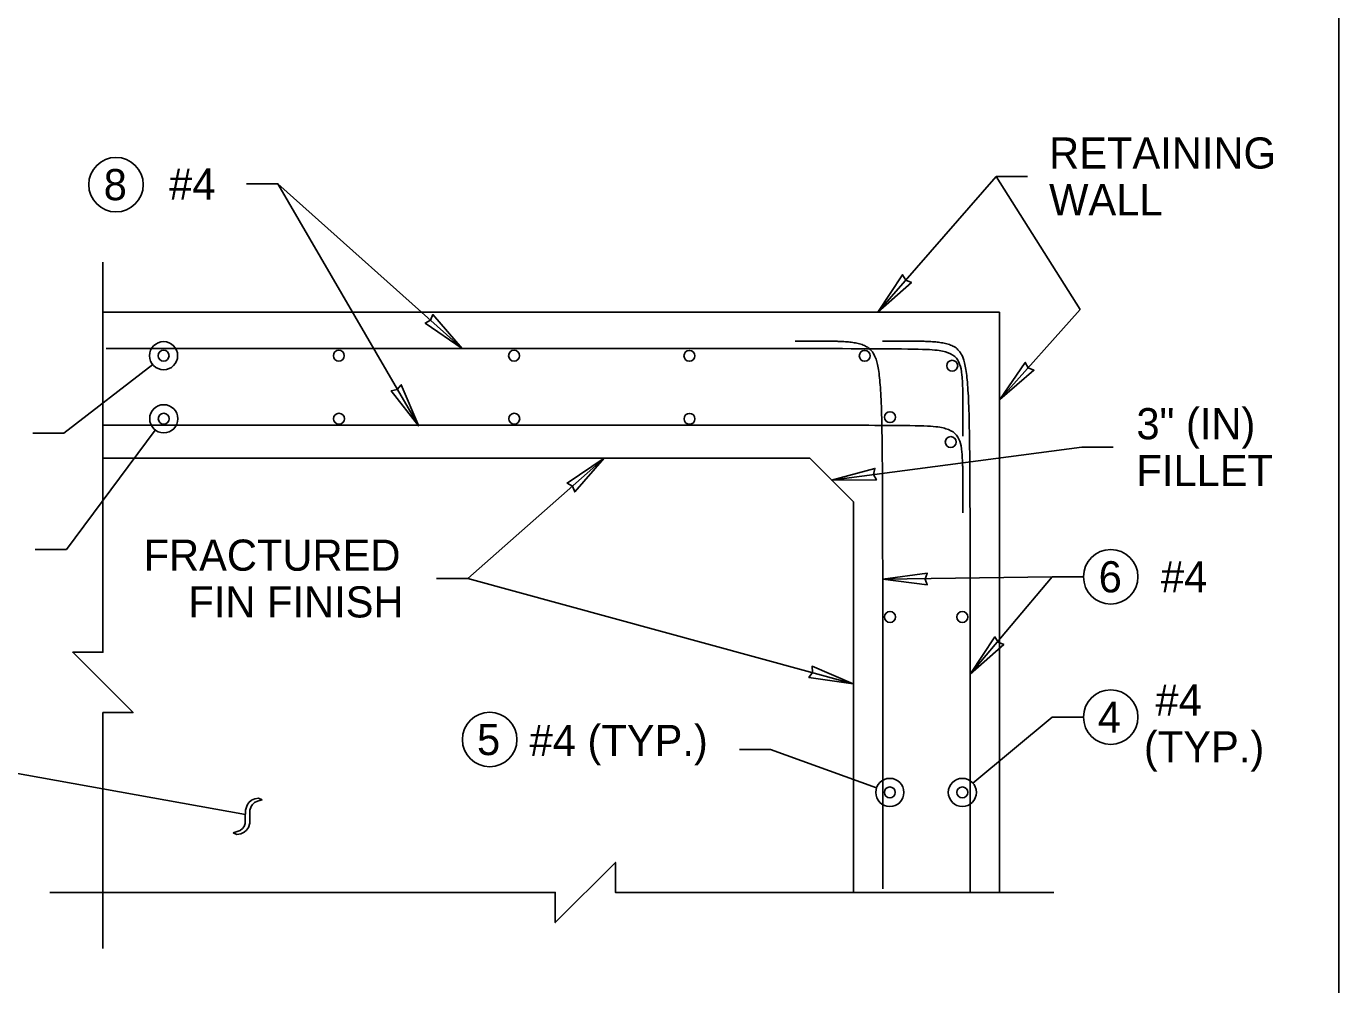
# Model space of a CAD drawing. Extents: x 99862 to 103680, y 99470 to 105076.
# Drawn here: x 102477 to 103151, y 103992 to 104485 of the extents above; entities that cross this region are included whole.
import ezdxf

# ---------------------------------------------------------------- set-up
doc = ezdxf.new("R2010")
doc.units = 0
for name, color, linetype in [('Level 1', 7, 'Continuous'), ('Level 14', 7, 'Continuous'), ('Level 15', 7, 'Continuous'), ('Level 2', 7, 'Continuous'), ('Level 20', 7, 'Continuous'), ('Level 34', 7, 'Continuous'), ('Level 35', 7, 'Continuous'), ('Level 36', 7, 'Continuous'), ('Level 38', 7, 'Continuous')]:
    doc.layers.add(name, color=color, linetype=linetype)

msp = doc.modelspace()

# ---------------------------------------------------------------- linework, layer by layer
at = {"layer": 'Level 1'}
msp.add_lwpolyline([(99862, 102999.5), (103151, 102999.5), (103151, 105075.5), (99862, 105075.5)], close=True, dxfattribs=at)
at = {"layer": 'Level 14'}
for points in [[(102516.3, 104010.95), (102516.3, 104132.04), (102531.79, 104132.04), (102500.82, 104163.02), (102516.3, 104163.02), (102516.3, 104363.37)], [(103004.71, 104039.64), (102779.54, 104039.64), (102779.54, 104055.12), (102748.57, 104024.15), (102748.57, 104039.64), (102489.1, 104039.64)]]:
    msp.add_lwpolyline(points, dxfattribs=at)
at = {"layer": 'Level 15'}
for p, q in [((102590.09, 104403.51), (102606.09, 104403.51)), ((102700.77, 104318.98), (102606.09, 104403.51)), ((102606.09, 104403.51), (102678.47, 104279.16)), ((102914.26, 104337.73), (102975.1, 104407.43)), ((102991.1, 104407.43), (102975.1, 104407.43)), ((103018.21, 104338.98), (102975.1, 104407.43)), ((102976.99, 104292.84), (103018.21, 104338.98)), ((102541.93, 104310.87), (102496.26, 104275.58)), ((102480.26, 104275.58), (102496.26, 104275.58)), ((102543.18, 104277.15), (102497.51, 104215.77)), ((102773.74, 104262.73), (102703.68, 104200.89)), ((103019.08, 104268.4), (102890.54, 104251.48)), ((103035.08, 104268.4), (103019.08, 104268.4)), ((102481.51, 104215.77), (102497.51, 104215.77)), ((102916.79, 104200.64), (103003.88, 104201.78)), ((102961.7, 104151.72), (103003.88, 104201.78)), ((103019.88, 104201.78), (103003.88, 104201.78)), ((102687.68, 104200.89), (102703.68, 104200.89)), ((102901.69, 104146.82), (102703.68, 104200.89)), ((102963.09, 104095.82), (103003.88, 104129.71)), ((103019.88, 104129.71), (103003.88, 104129.71)), ((102843.17, 104113.04), (102859.17, 104113.04)), ((102913.59, 104093.36), (102859.17, 104113.04)), ((102589.46, 104079.62), (102468.66, 104101.43)), ((102592.59, 104086.99), (102591.28, 104085.9)), ((102594.23, 104087.72), (102592.59, 104086.99)), ((102594.15, 104085.78), (102595.74, 104086.49)), ((102596.18, 104088.09), (102594.23, 104087.72)), ((102595.74, 104086.49), (102598.07, 104087.15)), ((102598.07, 104087.15), (102596.18, 104088.09)), ((102589.52, 104081.83), (102589.41, 104077.42)), ((102590.3, 104084.44), (102589.52, 104081.83)), ((102591.28, 104085.9), (102590.3, 104084.44)), ((102591.75, 104079.41), (102591.82, 104081.96)), ((102591.82, 104081.96), (102592.35, 104083.81)), ((102592.35, 104083.81), (102593.11, 104084.91)), ((102593.11, 104084.91), (102594.15, 104085.78)), ((102588.9, 104073.56), (102588.04, 104072.43)), ((102589.34, 104075), (102588.9, 104073.56)), ((102589.41, 104077.42), (102589.34, 104075)), ((102590.04, 104071.59), (102590.97, 104072.98)), ((102590.97, 104072.98), (102591.72, 104075.32)), ((102591.72, 104075.32), (102591.75, 104079.41)), ((102586.7, 104071.48), (102583.2, 104070.28)), ((102583.2, 104070.28), (102585.09, 104069.34)), ((102585.09, 104069.34), (102587.18, 104069.82)), ((102588.04, 104072.43), (102586.7, 104071.48)), ((102587.18, 104069.82), (102588.8, 104070.56)), ((102588.8, 104070.56), (102590.04, 104071.59))]:
    msp.add_line(p, q, dxfattribs=at)
for points in [[(102914.26, 104337.73), (102931.52, 104352.97), (102928.58, 104354.14), (102927.02, 104356.9)], [(102700.77, 104318.98), (102681.8, 104332.04), (102684.59, 104333.55), (102685.8, 104336.48)], [(102976.99, 104292.84), (102994.42, 104307.88), (102991.5, 104309.08), (102989.97, 104311.86)], [(102678.52, 104279.19), (102664.36, 104297.35), (102667.47, 104297.95), (102669.51, 104300.38)], [(102773.74, 104262.73), (102754.65, 104249.87), (102757.41, 104248.33), (102758.6, 104245.39)], [(102890.54, 104251.48), (102913.56, 104251.5), (102912.13, 104254.33), (102912.79, 104257.42)], [(102916.79, 104200.64), (102939.62, 104197.66), (102938.56, 104200.64), (102939.62, 104203.63)], [(102961.7, 104151.72), (102978.94, 104166.98), (102976, 104168.14), (102974.44, 104170.9)], [(102901.69, 104146.82), (102878.9, 104150.08), (102880.72, 104152.68), (102880.5, 104155.84)]]:
    msp.add_lwpolyline(points, close=True, dxfattribs=at)
for centre in [(102547.44, 104315.33), (102547.53, 104282.93), (102920.44, 104091.03), (102957.68, 104091.02)]:
    msp.add_circle(centre, 7.23, dxfattribs=at)
at = {"layer": 'Level 2'}
for p, q in [((102976.7, 104337.73), (102516.3, 104337.73)), ((102976.7, 104039.64), (102976.7, 104337.73)), ((102516.3, 104262.73), (102879.29, 104262.73)), ((102879.29, 104262.73), (102901.79, 104240.23)), ((102901.79, 104240.23), (102901.79, 104039.64))]:
    msp.add_line(p, q, dxfattribs=at)
at = {"layer": 'Level 20'}
for centre in [(102522.99, 104403.17), (103033.88, 104201.78), (103033.88, 104129.71), (102714.92, 104118.2)]:
    msp.add_circle(centre, 14, dxfattribs=at)
at = {"layer": 'Level 34'}
for centre, start, end in [((102547.44, 104315.33), 0, 180), ((102637.44, 104315.33), 0, 180), ((102727.44, 104315.33), 0, 180), ((102817.51, 104315.27), 0, 180), ((102907.54, 104315.27), 0, 180), ((102547.44, 104315.33), 180, 0), ((102637.44, 104315.33), 180, 0), ((102727.44, 104315.33), 180, 0), ((102817.51, 104315.27), 180, 0), ((102907.54, 104315.27), 180, 0), ((102952.47, 104310.17), 90, 270), ((102952.47, 104310.17), 270, 90), ((102951.71, 104270.95), 90, 270), ((102951.71, 104270.95), 270, 90), ((102957.68, 104181.14), 90, 270), ((102957.68, 104181.14), 270, 90), ((102957.68, 104091.02), 90, 270), ((102957.68, 104091.02), 270, 90)]:
    msp.add_arc(centre, 2.81, start, end, dxfattribs=at)
at = {"layer": 'Level 35'}
for centre, start, end in [((102547.53, 104282.93), 0, 180), ((102547.53, 104282.93), 180, 0), ((102637.53, 104282.93), 0, 180), ((102637.53, 104282.93), 180, 0), ((102727.53, 104282.93), 0, 180), ((102727.53, 104282.93), 180, 0), ((102817.56, 104282.91), 0, 180), ((102817.56, 104282.91), 180, 0), ((102920.54, 104283.75), 0, 180), ((102920.54, 104283.75), 180, 0), ((102920.53, 104181.14), 0, 180), ((102920.53, 104181.14), 180, 0), ((102920.44, 104091.03), 0, 180), ((102920.44, 104091.03), 180, 0)]:
    msp.add_arc(centre, 2.81, start, end, dxfattribs=at)
at = {"layer": 'Level 36'}
for points in [[(102871.79, 104322.83), (102884.92, 104322.83), (102898.04, 104322.83), (102916.79, 104322.83), (102916.79, 104304.08), (102916.79, 104188.75), (102916.79, 104041.51)], [(102916.7, 104322.83), (102929.82, 104322.83), (102942.95, 104322.83), (102961.7, 104322.83), (102961.7, 104304.08), (102961.7, 104188.02), (102961.7, 104039.64)]]:
    msp.add_open_spline(points, degree=4, dxfattribs=at)
at = {"layer": 'Level 38'}
for points in [[(102957.99, 104273.98), (102957.99, 104288.98), (102957.99, 104303.98), (102957.99, 104318.98), (102942.99, 104318.98), (102907.19, 104318.98), (102517.89, 104318.98)], [(102957.95, 104234.63), (102957.95, 104249.63), (102957.95, 104264.63), (102957.95, 104279.63), (102942.95, 104279.63), (102909.37, 104279.63), (102516.77, 104279.63)]]:
    msp.add_open_spline(points, degree=4, dxfattribs=at)

# ---------------------------------------------------------------- texts
at = {"layer": 'Level 20'}
for s, p in [('RETAINING ', (103002.25, 104411.43)), ('8', (102516.69, 104395.19)), ('#4 ', (102550.32, 104395.51)), ('WALL', (103002.25, 104387.43)), ('FRACTURED', (102537.17, 104204.89)), ('6', (103027.69, 104193.78)), ('#4 ', (103059.67, 104193.78)), ('FIN FINISH', (102560.15, 104180.89)), ('4', (103027.28, 104121.71)), ('5', (102708.43, 104110.2)), ('#4 (TYP.)', (102735.41, 104109.74))]:
    msp.add_text(s, height=16, dxfattribs=at).set_placement(p)
for s, p in [('3" (IN)', (103047.08, 104272.4)), ('FILLET', (103047.08, 104248.4)), (' #4 ', (103050.93, 104130.47)), ('(TYP.)', (103050.93, 104106.47))]:
    msp.add_text(s, height=16, rotation=360, dxfattribs=at).set_placement(p)

doc.saveas('drawing.dxf')
